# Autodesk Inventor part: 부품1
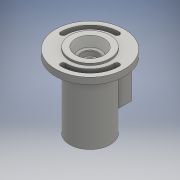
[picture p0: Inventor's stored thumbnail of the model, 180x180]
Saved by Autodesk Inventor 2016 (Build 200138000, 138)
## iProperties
Created: 2017-05
Part Number: 부품1
Material: 일반
Document SubType Name: Modeling
Designer: USER
Density: 1 g/cm^3
Appearance: 기본값
Author: USER
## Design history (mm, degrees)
sketch "스케치2"
  geometry: C1 r 53 at (0, 0); 1 further point
  constraints: 1 centre point, 1 coincident
  dimensions: "d0" = 106 diameter of C1
extrude "돌출1" new body sketch "스케치2" distance "d1" = 10; taper "d2" = 0 deg
sketch "스케치3"
  geometry: A1 r 41.5 centre (0, 0) between (0, 41.5) and (-41.5, 0); A2 r 4 centre (0, 41.5) between (0, 37.5) and (0, 45.5); A3 r 4 centre (-41.5, 0) between (-45.5, 0) and (-37.5, 0); A4 r 4 centre (41.5, 0) between (45.5, 0) and (37.5, 0); A5 r 4 centre (0, -41.5) between (0, -37.5) and (0, -45.5); A6 r 37.5 centre (0, 0) between (0, 37.5) and (-37.5, 0); A7 r 37.5 centre (0, 0) between (0, -37.5) and (37.5, 0); A8 r 45.5 centre (0, 0) between (0, 45.5) and (-45.5, 0); A9 r 45.5 centre (0, 0) between (0, -45.5) and (45.5, 0); 1 further point
  constraints: 20 point on circle, 9 centre point, 4 tangent, 3 coincident, 2 horizontal alignment, 2 vertical alignment
  dimensions: "d4" = 83 diameter of A1; "d5" = 8 diameter of A2; "d6" = 8 diameter of A3; "d7" = 8 diameter of A4; "d8" = 8 diameter of A5
extrude "돌출2" cut sketch "스케치3" distance "d9" = 10; taper "d10" = 0 deg
sketch "스케치4"
  geometry: C1 r 31 at (0, 0); 1 further point
  constraints: 1 centre point, 1 coincident
  dimensions: "d11" = 62 diameter of C1
extrude "돌출3" join sketch "스케치4" distance "d12" = 3; taper "d13" = 0 deg
sketch "스케치5"
  geometry: C1 r 31 at (0, 0); 1 further point
  constraints: 1 centre point, 1 coincident
  dimensions: "d14" = 62 diameter of C1
extrude "돌출4" join sketch "스케치5" distance "d15" = 102; taper "d16" = 0 deg
node "작업 평면1"
sketch "스케치6"
  geometry: L1 (37.5, 10)-(37.5, 0) reference; L2 (37.5, 0)-(31, 0) reference; L3 (31, 0)-(31, -102) reference; L4 (31, -102)-(-31, -102) reference; L5 (-31, -102)-(-31, 0) reference; L6 (-31, 0)-(-37.5, 0) reference; L7 (-37.5, 0)-(-37.5, 10) reference; L8 (-37.5, 10)-(-31, 10) reference; L9 (-31, 10)-(-31, 13) reference; L10 (-31, 13)-(31, 13) reference; L11 (31, 13)-(31, 10) reference; L12 (31, 10)-(37.5, 10) reference; L13 (-53, 0)-(-53, 10) reference; L14 (-53, 10)-(-45.5, 10) reference; L15 (-45.5, 10)-(-45.5, 0) reference; L16 (-45.5, 0)-(-53, 0) reference; L17 (53, 10)-(53, 0) reference; L18 (53, 0)-(45.5, 0) reference; L19 (45.5, 0)-(45.5, 10) reference; L20 (45.5, 10)-(53, 10) reference; L21 (0, -102)-(0, 13); L22 (31, 13)-(-31, 13) reference; L23 (21, -102)-(21, -93); L24 (21, -93)-(24, -93); L25 (24, -93)-(24, -90); L26 (24, -90)-(20, -90); L27 (20, -90)-(20, -81); L28 (20, -81)-(17.5, -81); L29 (17.5, -81)-(17.5, -77.75); L30 (17.5, -77.75)-(18.5, -77.75); L31 (18.5, -77.75)-(18.5, -76); L32 (18.5, -76)-(17.5, -76); L33 (17.5, -76)-(17.5, -65); L34 (17.5, -65)-(26, -65); L35 (26, -65)-(26, -27); L36 (26, -27)-(17.5, -27); L37 (17.5, -27)-(17.5, -16); L38 (17.5, -16)-(16, -16); L39 (16, -16)-(16, -11); L40 (16, -11)-(10, -11); L41 (10, -11)-(10, -8.3); L42 (10, -8.3)-(12.5, -8.3); L43 (12.5, -8.3)-(12.5, -1); L44 (12.5, -1)-(16, -1); L45 (16, -1)-(22, 13); 1 further point
  constraints: 48 end point, 17 perpendicular, 4 point on line, 2 horizontal, 2 midpoint, 2 vertical
  dimensions: "d18" = 42 diameter of L23 L21; "d19" = 9 distance of L23.start L23.end; "d20" = 48 diameter of L25 L21; "d21" = 40 diameter of L27 L21; "d22" = 3 distance of L24.end L25.end; "d23" = 35 diameter of L29 L21; "d24" = 21 distance between parallel lines of L28 L4; "d25" = 37 diameter of L31 L21; "d26" = 1.75 distance of L30.end L31.end; "d27" = 26 distance between parallel lines of L4 L32; "d28" = 11 distance of L32.end L33.end; "d29" = 35 diameter of L33 L21; "d30" = 52 diameter of L35 L21; "d31" = 38 distance of L34.end L35.end; "d32" = 11 distance of L36.end L37.end; "d33" = 25 diameter of L43 L21; "d34" = 7.3 distance of L42.end L43.end; "d35" = 2.7 distance of L40.end L41.end; "d36" = 20 diameter of L41 L21; "d37" = 5 distance of L38.end L39.end; "d39" = 32 diameter of L39 L21; "d40" = 32 diameter of L44.end L21; "d41" = 44 diameter of L45.end L21
revolve "회전1" sketch "스케치6" stored, may be unused: angle "d42" = 90 deg
feature "스레드1" dims "d43" = 10, "d44" = 0
chamfer "모따기1" distance "d45" = 1; stored, may be unused: second distance "d46" = 2, angle "d47" = 45 deg
chamfer "모따기2" distance "d48" = 1; stored, may be unused: second distance "d49" = 2, angle "d50" = 45 deg
chamfer "모따기3" distance "d51" = 0.7; stored, may be unused: second distance "d52" = 2, angle "d53" = 30 deg
fillet "모깎기1" dims "d54" = 3
fillet "모깎기2" dims "d55" = 3
fillet "모깎기3" dims "d56" = 3
fillet "모깎기4" dims "d57" = 0.3
node "작업 평면2"
sketch "스케치7"
  geometry: L1 (-31, 0)-(-31, -102) reference; L2 (-31, -102)-(31, -102) reference; L3 (31, 0)-(31, -102) reference; L4 (-20, -71)-(20, -71); L5 (20, -71)-(20, -21); L6 (20, -21)-(-20, -21); L7 (-20, -21)-(-20, -71); 3 further points
  constraints: 8 end point, 2 midpoint, 2 parallel, 1 horizontal, 1 perpendicular, 1 vertical alignment
  dimensions: "d59" = 31 distance between parallel lines of L4 L2; "d60" = 40 distance of L4.start L4.end; "d61" = 50 distance of L4.end L5.end
extrude "돌출5" join sketch "스케치7" stored distance "d62" = 102; taper "d63" = 0 deg
sketch "스케치8"
  geometry: L1 (11, 62)-(-11, 62); L2 (-11, 62)-(-11, 30); L3 (-11, 30)-(11, 30); L4 (11, 30)-(11, 62); L5 (20, 71)-(-20, 71) reference; L6 (11, 46)-(-11, 46); L7 (31, 102)-(-31, 102) reference; 3 further points
  constraints: 10 end point, 4 midpoint, 2 parallel, 1 horizontal, 1 perpendicular, 1 vertical alignment
  dimensions: "d64" = 22 distance of L1.start L1.end; "d65" = 32 distance of L1.end L2.end; "d66" = 56 distance between parallel lines of L7 L6
extrude "돌출6" cut sketch "스케치8" stored distance "d67" = 102; taper "d68" = 0 deg
node "솔리드1"
node "절단 모서리 투영1"
other parameters: "d17" = 0, "d58" = 44
